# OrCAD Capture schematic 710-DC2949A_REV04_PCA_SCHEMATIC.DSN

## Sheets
1 LT8253A: size Custom; company: ANALOG DEVICES; note: DEMO BOARD BILL OF MATERIALS; note: 2MHz 45W AUTOMOTIVE USB TYPE-C PD CHARGER
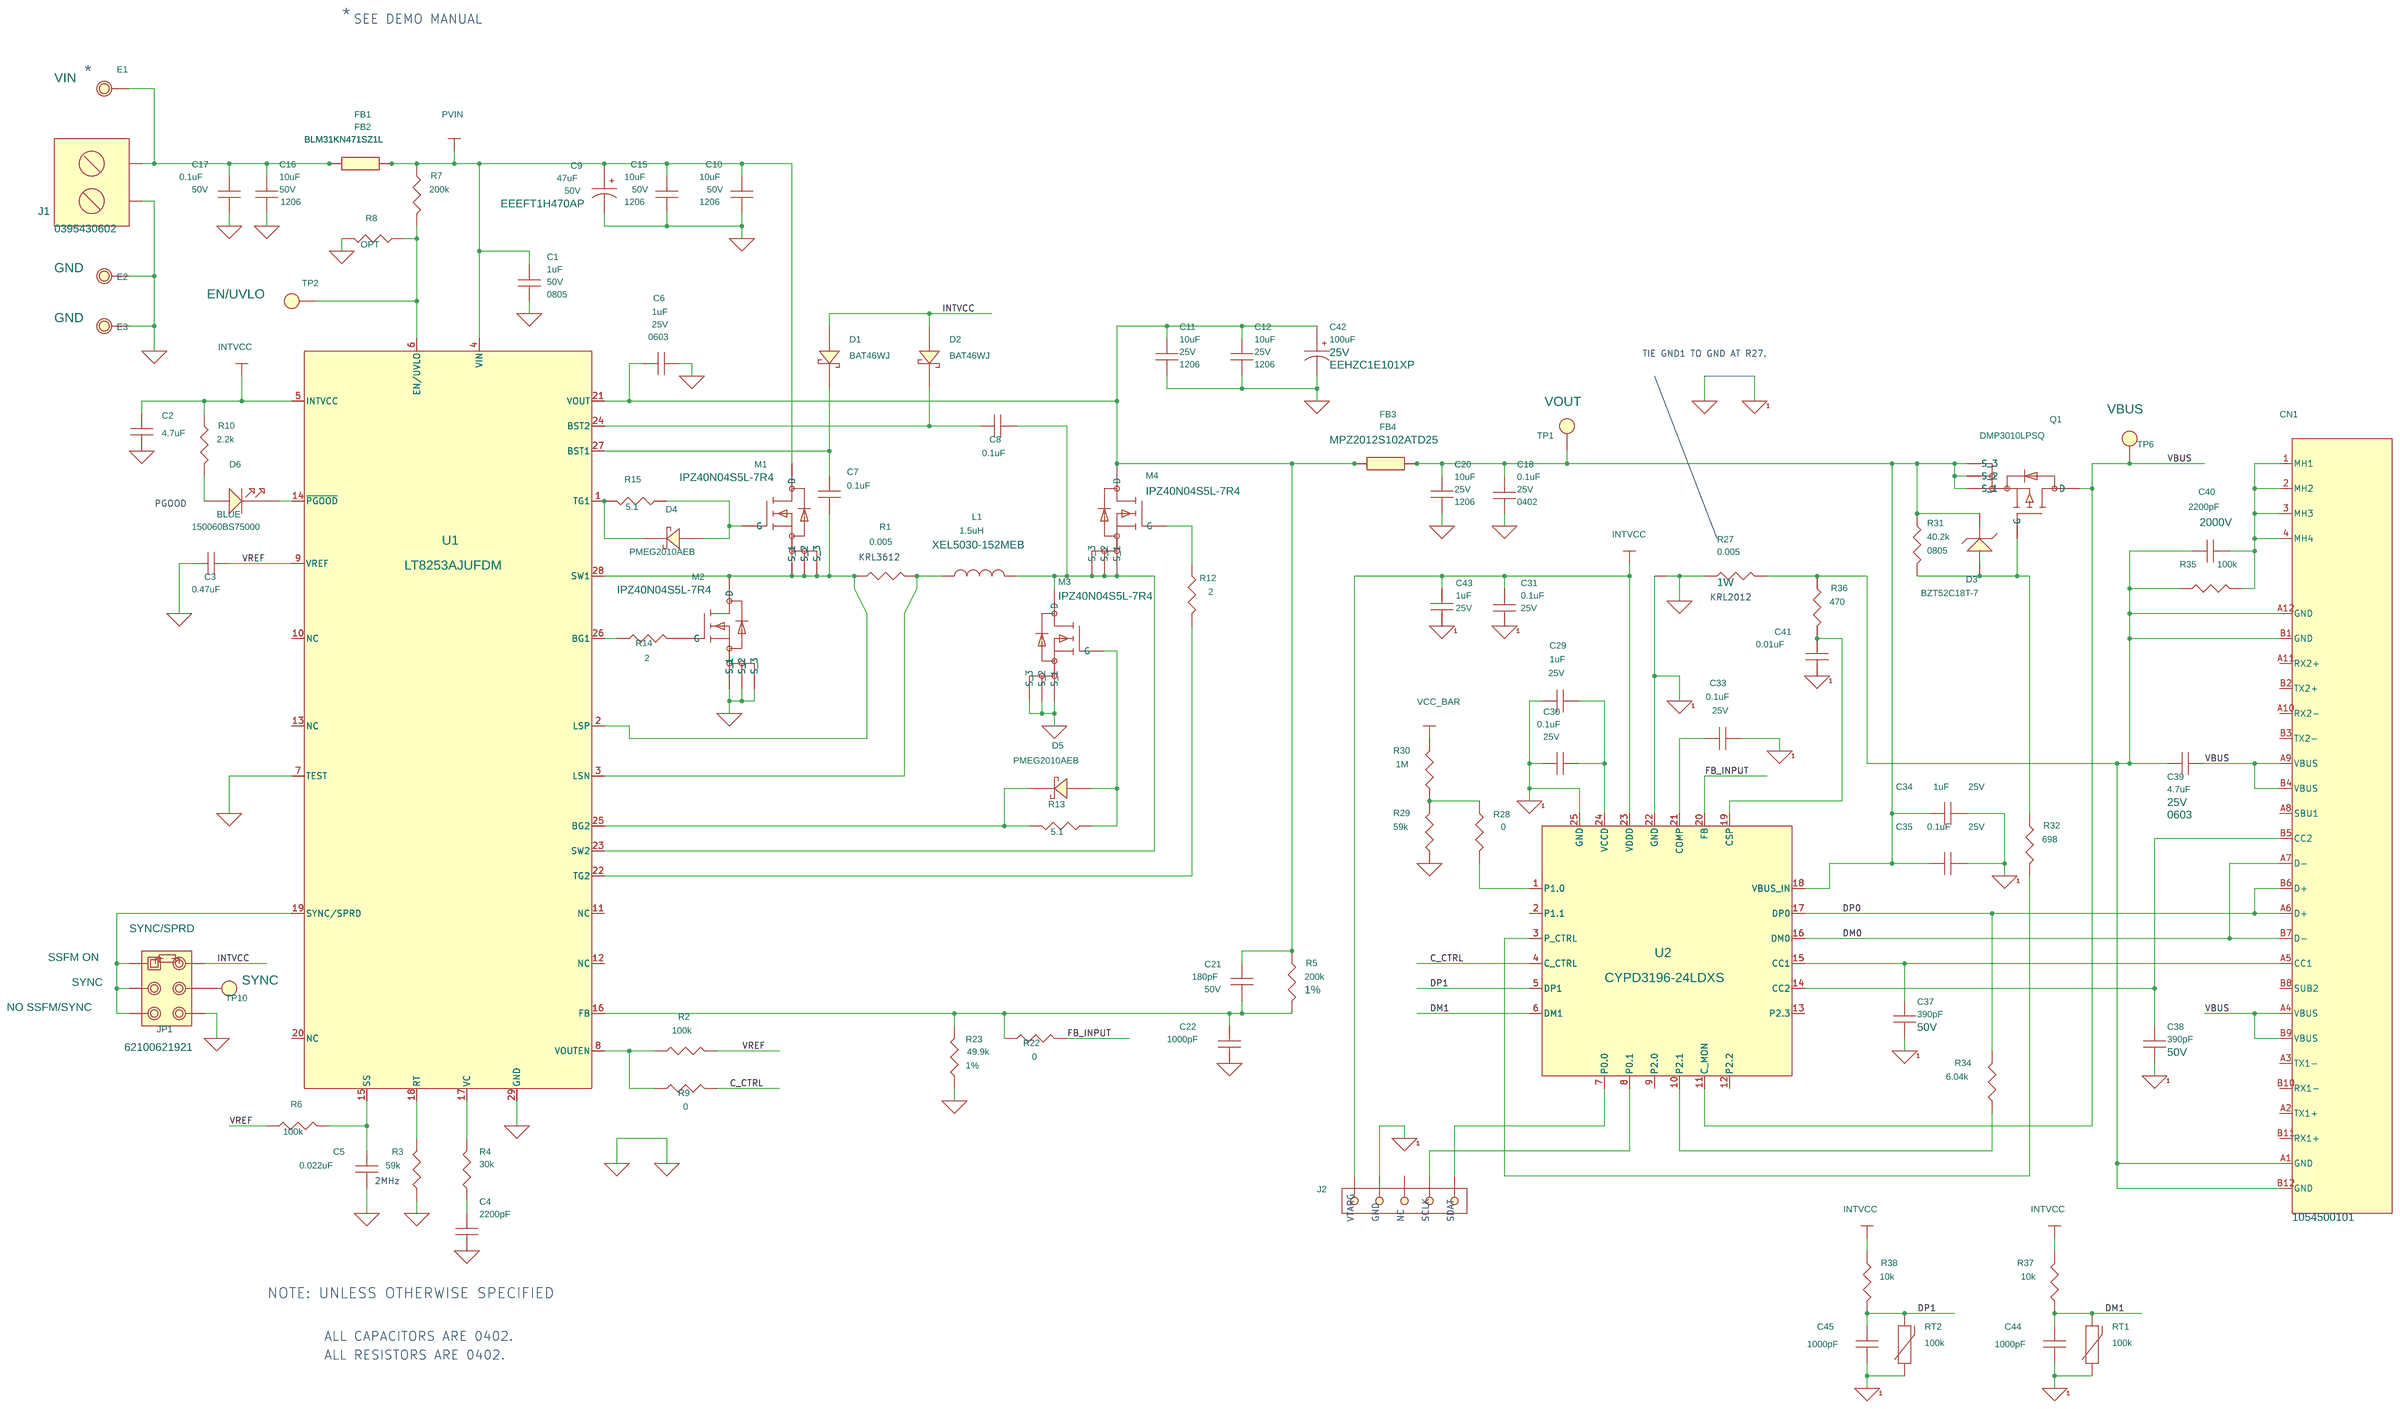
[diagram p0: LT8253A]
2 HARDWARE
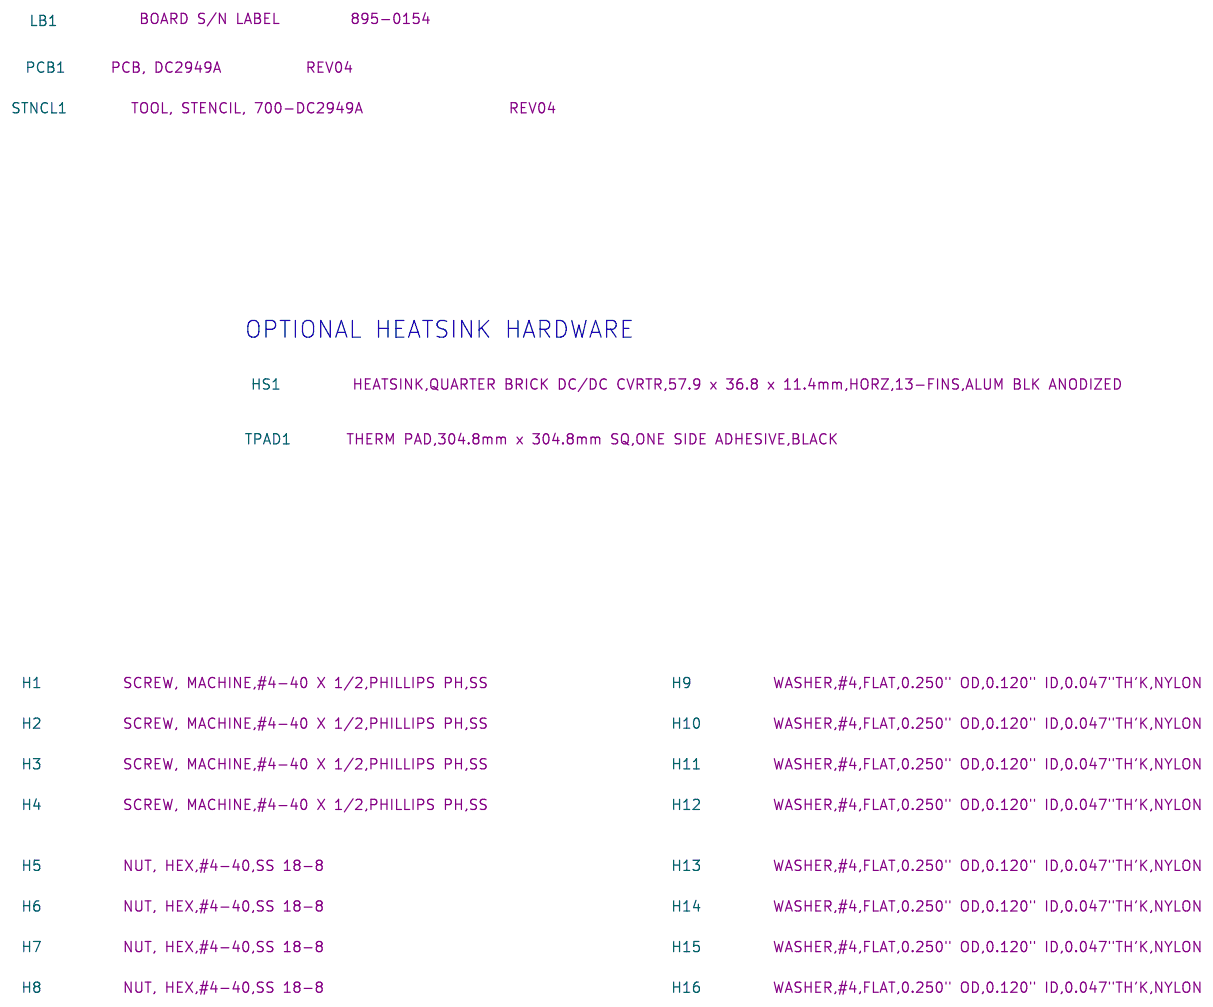
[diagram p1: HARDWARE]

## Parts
sheet HARDWARE
H1  SCREW, MACHINE
H2  SCREW, MACHINE
H3  SCREW, MACHINE
H4  SCREW, MACHINE
H5  NUT, HEX
H6  NUT, HEX
H7  NUT, HEX
H8  NUT, HEX
H9  WASHER,#4,FLAT
H10  WASHER,#4,FLAT
H11  WASHER,#4,FLAT
H12  WASHER,#4,FLAT
H13  WASHER,#4,FLAT
H14  WASHER,#4,FLAT
H15  WASHER,#4,FLAT
H16  WASHER,#4,FLAT
HS1  HEATSINK
LB1  LABEL  [895-0154_REV01]
PCB1  PCB, DC2949A
STNCL1  TOOL, STENCIL, 700-DC2949A
TPAD1  THERM PAD  [UNASSIGNED]
sheet LT8253A
C1  1uF  [CC0805N]
C2  4.7uF  [CC0402N]
C3  0.47uF  [CC0402N]
C4  2200pF  [CC0402N]
C5  0.022uF  [CC0402N]
C6  1uF  [CC0603N]
C7  0.1uF  [CC0402N]
C8  0.1uF  [CC0402N]
C9  47uF  [PANASONIC_FT_6.3X5.8]
C10  10uF  [CC1206N]
C11  10uF  [CC1206N]
C12  10uF  [CC1206N]
C15  10uF  [CC1206N]
C16  10uF  [CC1206N]
C17  0.1uF  [CC0402N]
C18  0.1uF  [CC0402N]
C20  10uF  [CC1206N]
C21  180pF  [CC0402N]
C22  1000pF  [CC0402N]
C29  1uF  [CC0402N]
C30  0.1uF  [CC0402N]
C31  0.1uF  [CC0402N]
C33  0.1uF  [CC0402N]
C34  1uF  [CC0402N]
C35  0.1uF  [CC0402N]
C37  390pF  [CC0402N]
C38  390pF  [CC0402N]
C39  4.7uF  [CC0603N]
C40  2200pF  [CC1808N]
C41  0.01uF  [CC0402N]
C42  100uF  [PANASONIC_ZC_6.3X7.7]
C43  1uF  [CC0402N]
C44  1000pF  [CC0402N]
C45  1000pF  [CC0402N]
CN1  USB3.1  [MOLEX-1054500101]
D1  BAT46WJ  [SOD-323F-N]
D2  BAT46WJ  [SOD-323F-N]
D3  BZT52C18T-7  [SOD-523N]
D4  PMEG2010AEB  [SOD-523N]
D5  PMEG2010AEB  [SOD-523N]
D6  BLUE  [LED_0603]
E1  TEST POINT  [MILLMAX2308]
E2  TEST POINT  [MILLMAX2308]
E3  TEST POINT  [MILLMAX2308]
FB1  470 OHMS@100MHz  [IND1206N]
FB2  470 OHMS@100MHz  [IND1206N]
FB3  1k OHM@100MHz  [IND0805N]
FB4  1k OHM@100MHz  [IND0805N]
J1  TERM. BLOCK  [MOLEX-0395430602]
J2  HDR  [HD1X5-100]
JP1  HDR  [WURTH-62100621921]
L1  1.5uH  [COILCRAFT-XEL5030]
M1  IPZ40N04S5L-7R4  [INFINEON-PG-TSDSON-8-32]
M2  IPZ40N04S5L-7R4  [INFINEON-PG-TSDSON-8-32]
M3  IPZ40N04S5L-7R4  [INFINEON-PG-TSDSON-8-32]
M4  IPZ40N04S5L-7R4  [INFINEON-PG-TSDSON-8-32]
N1  KELVIN NET TIE  [KELVIN-NET-TIE]
Q1  DMP3010LPSQ  [DIODES-POWERDI5060-8]
R1  0.005  [SUSUMU-KRL3216]
R2  100k  [CR0402N]
R3  59k  [CR0402N]
R4  30k  [CR0402N]
R5  200k  [CR0402N]
R6  100k  [CR0402N]
R7  200k  [CR0402N]
R8  OPT  [CR0402N]
R9  0  [CR0402N]
R10  2.2k  [CR0402N]
R12  2  [CR0402N]
R13  5.1  [CR0402N]
R14  2  [CR0402N]
R15  5.1  [CR0402N]
R22  0  [CR0402N]
R23  49.9k  [CR0402N]
R27  0.005  [SUSUMU-KRL2012]
R28  0  [CR0402N]
R29  59k  [CR0402N]
R30  1M  [CR0402N]
R31  40.2k  [CR0805N]
R32  698  [CR0402N]
R34  6.04k  [CR0402N]
R35  100k  [CR0402N]
R36  470  [CR0402N]
R37  10k  [CR0402N]
R38  10k  [CR0402N]
RT1  100k  [CR0603N]
RT2  100k  [CR0603N]
TP1  TEST PAD  [PADSTYLE1]
TP2  TEST PAD  [PADSTYLE1]
TP6  TEST PAD  [PADSTYLE1]
TP10  TEST PAD  [PADSTYLE1]
U1  LT8253AJUFDM  [LTC-UFDM-28-1682]
U2  CYPD3196-24LDXS  [CYPRESS-CYPD3196-24LDXS]
XJP1  SHUNT

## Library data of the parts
H1-H4 = BLANK_PINLESS_MECHANICAL_PART: SCREW, MACHINE,#4-40 X 1/2,PHILLIPS PH,SS; CLASS: MECHANICAL PART; Inventory Qty: 17916; Manufacturer: PENCOM; Manufacturer PN: SC3389; PART_NUMBER: 760-0065
H5-H8 = BLANK_PINLESS_MECHANICAL_PART: NUT, HEX,#4-40,SS 18-8; CLASS: MECHANICAL PART; Inventory Qty: 8116; Manufacturer: PENCOM; Manufacturer PN: NU1043; PART_NUMBER: 761-0005
H9-H16 = BLANK_PINLESS_MECHANICAL_PART: WASHER,#4,FLAT,0.250" OD,0.120" ID,0.047"TH'K,NYLON; CLASS: DISCRETE; Inventory Qty: 4520; Manufacturer: KEYSTONE; Manufacturer PN: 345; PART_NUMBER: 762-0024
HS1 = BLANK_MECHANICAL_PART: HEATSINK,QUARTER BRICK DC/DC CVRTR,57.9 x 36.8 x 11.4mm,HORZ,13-FINS,ALUM BLK ANODIZED; CLASS: DISCRETE; Inventory Qty: 440; Manufacturer: Wakefield-Vette; Manufacturer PN: 537-45AB; PART_NUMBER: 930-0009
LB1 = BLANK_LABEL: LABEL SPEC, DEMO BOARD SERIAL NUMBER; Inventory Qty: 0; Manufacturer: BRADY; Manufacturer PN: THT-96-717-10; PART_FIELD_01: BOARD S/N LABEL; PART_NUMBER: 895-0154
PCB1 = BLANK_PCB_PART: BOM Notes: REV04; CLASS: DISCRETE; Inventory Qty: 180; Manufacturer: ADI APPROVED SUPPLIER; Manufacturer PN: 600-DC2949A; PART_NUMBER: 600-DC2949A
STNCL1 = BLANK_STENCIL_PART: BOM Notes: REV04; CLASS: DISCRETE; Inventory Qty: 0; Manufacturer: ADI APPROVED SUPPLIER; Manufacturer PN: 830-DC2949A; PART_NUMBER: 830-DC2949A
TPAD1 = BLANK_MECHANICAL_PART: THERM PAD,304.8mm x 304.8mm SQ,ONE SIDE ADHESIVE,BLACK; CLASS: DISCRETE; Inventory Qty: 5; Manufacturer: HENKEL; Manufacturer PN: SP1200-0.009-00-1212; PART_NUMBER: 930-1000; Package Size: 304.80mm x 304.80mm
C1 = CAP: CAP.,1uF,X7R,50V,10%,0805,AEC-Q200; CLASS: DISCRETE; Dielectric Type: X7R; FPLIST: CC0805N,CC0805L,CC0805M; Inventory Qty: 8866; Manufacturer: MURATA; Manufacturer PN: GCM21BR71H105KA03L; PART_NUMBER: 150-1750; Package Size: 0805; Rated Voltage: 50V; Temperature Coefficient: X7R; Tolerance: 10%
C2 = CAP: CAP.,4.7uF,X5R,6.3V,20%,0402,AEC-Q200; CLASS: DISCRETE; Dielectric Type: X5R; FPLIST: CC0402N,CC0402M,CC0402L; Inventory Qty: 10830; Manufacturer: Taiyo Yuden; Manufacturer PN: JMK105BBJ475MVHF; PART_NUMBER: 150-1751; Package Size: 0402; Rated Voltage: 6.3V; Temperature Coefficient: X5R; Tolerance: 20%
C3 = CAP: CAP.,0.47uF,X5R,25V,10%,0402,AEC-Q200, NO SUBS. ALLOWED; CLASS: DISCRETE; Dielectric Type: X5R; FPLIST: CC0402N,CC0402L,CC0402M; Inventory Qty: 11830; Manufacturer: MURATA; Manufacturer PN: GRT155R61E474KE01D; PART_NUMBER: 150-2591; Package Size: 0402; Rated Voltage: 25V; Temperature Coefficient: X5R; Tolerance: 10%
C4 = CAP: CAP.,2200pF,X7R,50V,10%,0402,AEC-Q200; CLASS: DISCRETE; Dielectric Type: X7R; FPLIST: CC0402N,CC0402L,CC0402M,CC0402N_022,CC0402L_022,CC0402M_022; Inventory Qty: 49890; Manufacturer: KEMET; Manufacturer PN: C0402C222K5RACAUTO; PART_NUMBER: 150-1773; Package Size: 0402; Rated Voltage: 50V; Temperature Coefficient: X7R; Tolerance: 10%
C5 = CAP: CAP.,0.022uF,X7R,25V,10%,0402,AEC-Q200; CLASS: DISCRETE; Dielectric Type: X7R; FPLIST: CC0402N,CC0402M,CC0402L; Inventory Qty: 23940; Manufacturer: MURATA; Manufacturer PN: GCM155R71E223KA55D; PART_NUMBER: 150-1753; Package Size: 0402; Rated Voltage: 25V; Temperature Coefficient: X7R; Tolerance: 10%
C6 = CAP: CAP.,1uF,X7R,25V,10%,0603,AEC-Q200; CLASS: DISCRETE; Dielectric Type: X7R; FPLIST: CC0603N,CC0603L,CC0603M; Inventory Qty: 54674; Manufacturer: MURATA; Manufacturer PN: GCM188R71E105KA64D; PART_NUMBER: 150-0291; Package Size: 0603; Rated Voltage: 25V; Tolerance: 10%
C7 C8 = CAP: CAP.,0.1uF,X7R,16V,10%,0402,AEC-Q200; CLASS: DISCRETE; Dielectric Type: X7R; FPLIST: CC0402N,CC0402L,CC0402M; Inventory Qty: 23525; Manufacturer: MURATA; Manufacturer PN: GCM155R71C104KA55D; PART_NUMBER: 150-0506; Package Size: 0402; Rated Voltage: 16V; Tolerance: 10%
C9 = CAP_P_ALT: CAP.,47uF,ALUM ELECT,50V,20%,6.3x5.8mm SMD,RADIAL,AEC-Q200; CLASS: DISCRETE; Dielectric Type: ALUM ELECT; Inventory Qty: 2350; Manufacturer: PANASONIC; Manufacturer PN: EEEFT1H470AP; PART_NUMBER: 150-1754; Package Size: 6.3x5.8mm SMD,RADIAL; Package Type: Surface Mount; Rated Voltage: 50V; Tolerance: 20%
C10 C15 C16 = CAP: CAP.,10uF,X5R,50V,10%,1206,AEC-Q200; CLASS: DISCRETE; Dielectric Type: X5R; FPLIST: CC1206N,CC1206L,CC1206M; Inventory Qty: 9550; Manufacturer: MURATA; Manufacturer PN: GRT31CR61H106KE01L; PART_NUMBER: 150-1755; Package Size: 1206; Package Type: SMD; Rated Voltage: 50V; Tolerance: 10%
C11 C12 C20 = CAP: CAP.,10uF,X7R,25V,10%,1206,AEC-Q200; CLASS: DISCRETE; Dielectric Type: X7R; FPLIST: CC1206N,CC1206L,CC1206M; Inventory Qty: 14272; Manufacturer: TAIYO YUDEN; Manufacturer PN: TMK316AB7106KLHT; PART_NUMBER: 150-2466; Package Size: 1206; Package Type: SMD; Rated Voltage: 25V; Tolerance: 10%
C17 = CAP: CAP.,0.1uF,X7R,50V,10%,0402,AEC-Q200; CLASS: DISCRETE; Dielectric Type: X7R; FPLIST: CC0402N,CC0402L,CC0402M; Inventory Qty: 75030; Manufacturer: MURATA; Manufacturer PN: GCM155R71H104KE02D; PART_NUMBER: 150-2620; Package Size: 0402; Rated Voltage: 50V; Temperature Coefficient: X7R; Tolerance: 10%
C18 C30 C31 C33 C35 = CAP: CAP.,0.1uF,X7R,25V,10%,0402,AEC-Q200; CLASS: DISCRETE; Dielectric Type: X7R; FPLIST: CC0402N,CC0402L,CC0402M; Inventory Qty: 23030; Manufacturer: MURATA; Manufacturer PN: GCM155R71E104KE02D; PART_NUMBER: 150-1756; Package Size: 0402; Rated Voltage: 25V; Temperature Coefficient: X7R; Tolerance: 10%
C21 = CAP: CAP.,180pF,C0G/NP0,50V,5%,0402; CLASS: DISCRETE; Dielectric Type: C0G/NP0; FPLIST: CC0402N,CC0402L,CC0402M; Inventory Qty: 89552; Manufacturer: MURATA; Manufacturer PN: GRM1555C1H181JA01D; PART_NUMBER: 150-1703; Package Size: 0402; Rated Voltage: 50V; Temperature Coefficient: C0G; Tolerance: 5%
C22 C44 C45 = CAP: CAP.,1000pF,X7R,50V,10%,0402,AEC-Q200; CLASS: DISCRETE; Dielectric Type: X7R; Inventory Qty: 13560; Manufacturer: MURATA; Manufacturer PN: GCM155R71H102KA37D; PART_NUMBER: 150-1752; Package Size: 0402; Package Type: SMD; Rated Voltage: 50V; Tolerance: 10%
C29 C34 C43 = CAP: CAP.,1uF,X5R,25V,10%,0402,AEC-Q200; CLASS: DISCRETE; Dielectric Type: X5R; FPLIST: CC0402N,CC0402L,CC0402M; Inventory Qty: 31250; Manufacturer: MURATA; Manufacturer PN: GRT155R61E105KE01D; PART_NUMBER: 150-0749; Package Size: 0402; Rated Voltage: 25V; Tolerance: 10%
C37 C38 = CAP: CAP.,390pF,X7R,50V,10%,0402,AEC-Q200; CLASS: DISCRETE; Dielectric Type: X7R; Inventory Qty: 13660; Manufacturer: KEMET; Manufacturer PN: C0402C391K5RACAUTO; PART_NUMBER: 150-1757; Package Size: 0402; Package Type: SMD/SMT; Rated Voltage: 50V; Tolerance: 10%
C39 = CAP: CAP.,4.7uF,X5R,25V,10%,0603,AEC-Q200, NO SUBS. ALLOWED; CLASS: DISCRETE; Dielectric Type: X5R; FPLIST: CC0603N,CC0603L,CC0603M; Inventory Qty: 13830; Manufacturer: MURATA; Manufacturer PN: GRT188R61E475KE13D; PART_NUMBER: 150-2589; Package Size: 0603; Rated Voltage: 25V; Tolerance: 10%
C40 = CAP: CAP.,2200pF,X7R,2000V,10%,1808; CLASS: DISCRETE; Dielectric Type: X7R; Inventory Qty: 6680; Manufacturer: AVX; Manufacturer PN: 1808GC222KAT1A; PART_NUMBER: 150-1760; Package Size: 1808; Rated Voltage: 2000V; Temperature Coefficient: X7R; Tolerance: 10%
C41 = CAP: CAP.,0.01uF,X7R,25V,10%,0402,AEC-Q200; CLASS: DISCRETE; Dielectric Type: X7R; FPLIST: CC0402N,CC0402L,CC0402M; Inventory Qty: 27993; Manufacturer: MURATA; Manufacturer PN: GCM155R71E103KA37D; PART_NUMBER: 150-0517; Package Size: 0402; Rated Voltage: 25V; Tolerance: 10%
C42 = CAP_P_ALT: CAP.,100uF,HBRID,25V,20%,6.3x7.7mm,D8,SMD,RADIAL,AEC-Q200; CLASS: DISCRETE; Dielectric Type: HBRID; Inventory Qty: 1340; Manufacturer: PANASONIC; Manufacturer PN: EEHZC1E101XP; PART_NUMBER: 150-1758; Package Size: 6.3x7.7mm,D8,SMD,RADIAL; Package Type: Surface Mount; Rated Voltage: 25V; Tolerance: 20%
CN1 = MOLEX-1054500101_ALT1: CONN.,USB3.1,RCPT,24POS,1PORT,0.5mm,R/A,HORZ,SMT,TYPE C; CLASS: IO; Inventory Qty: 4028; Manufacturer: MOLEX; Manufacturer PN: 1054500101; PART_NUMBER: 250-0769
D1 D2 = DIODE_SCHOTTKY_A_ALT: DIODE,SCHOTTKY,100V,250mA,SOD-323F,AEC-Q101; CLASS: DISCRETE; FPLIST: SOD-323F-N,SOD-323F-L,SOD-323F-M; Inventory Qty: 6994; Manufacturer: NEXPERIA; Manufacturer PN: BAT46WJ,115; Max Forward Current or Rated Power: 250mA; PART_NUMBER: 210-0235; Package Type: SOD-323F; Rated Voltage or Zener Voltage: 100V
D3 = ZENER_ALT: DIODE,ZENER,18V,300mW,SOD-523,AEC-Q101; CLASS: DISCRETE; FPLIST: SOD-523N,SOD-523L,SOD-523M; Inventory Qty: 960; Manufacturer: DIODES INC.; Max Forward Current or Rated Power: 300mW; PART_NUMBER: 210-0493; Package Size: SC-79, SOD-523; Package Type: SOD-523; Rated Voltage or Zener Voltage: 18V
D4 D5 = DIODE_SCHOTTKY_A_ALT: DIODE,SCHOTTKY,20V,1A,SOD-523,AEC-Q101; CLASS: DISCRETE; Inventory Qty: 4584; Manufacturer: NEXPERIA; Manufacturer PN: PMEG2010AEB,115; PART_NUMBER: 210-0272; Package Size: SOD-523; Package Type: SOD-523; Rated Voltage or Zener Voltage: 20V
D6 = LED_ALT: LED,BLUE,WATERCLEAR,0603; CLASS: DISCRETE; Inventory Qty: 4418; Manufacturer: WURTH ELEKTRONIK; Manufacturer PN: 150060BS75000; PART_NUMBER: 270-0092; Package Size: 0603; Package Type: 0603
E1 = TEST_POINT_.156_MILL-MAX_2308_A: TEST POINT,TURRET,0.064" MTG. HOLE,PCB 0.062" THK; CLASS: IO; Inventory Qty: 918180; Manufacturer: MILL-MAX; Manufacturer PN: 2308-2-00-80-00-00-07-0; PART_FIELD_1: VIN; PART_FIELD_2: 9V-18V; PART_NUMBER: 260-0004
E2 E3 = TEST_POINT_.156_MILL-MAX_2308_A: TEST POINT,TURRET,0.064" MTG. HOLE,PCB 0.062" THK; CLASS: IO; Inventory Qty: 918180; Manufacturer: MILL-MAX; Manufacturer PN: 2308-2-00-80-00-00-07-0; PART_FIELD_1: GND; PART_NUMBER: 260-0004
FB1 FB2 = FERRITEBEAD_ALT1: IND.,470 OHMS@100MHz,FERRITE BEAD,25%,4A,20mOHMS,1206,AEC-Q200; CLASS: DISCRETE; FPLIST: IND1206N,IND1206L,IND1206M; Inventory Qty: 10352; Manufacturer: MURATA; Manufacturer PN: BLM31KN471SZ1L; PART_NUMBER: 200-0775; Package Size: 1206; Tolerance: 25%
FB3 FB4 = FERRITEBEAD_ALT1: IND.,1k OHM@100MHz,FERRITE BEAD,25%,1.5A,150mOHMS,0805,AEC-Q200; CLASS: DISCRETE; FPLIST: IND0805N,IND0805L,IND0805M; Inventory Qty: 24204; Manufacturer: TDK; Manufacturer PN: MPZ2012S102ATD25; PART_NUMBER: 200-0508; Package Size: 0805; Tolerance: 25%
J1 = TERMINAL_BLOCK_WITH_SCREW: CONN.,TERM. BLOCK,1x2,5mm,SIDE ENTRY,VERT,THT; CLASS: IO; Inventory Qty: 1350; Manufacturer: MOLEX; Manufacturer PN: 0395430602; PART_NUMBER: 250-0936
J2 = HDR1X5: CONN.,HDR,MALE,1x5,2.54mm,VERT,ST,THT; CLASS: IO; FPLIST: HD1X5-100,HDR-TSW-105-07-L-S; Inventory Qty: 10560; Manufacturer: SAMTEC; Manufacturer PN: TSW-105-07-L-S; PART_NUMBER: 250-0599
JP1 = HDR2X3_ALT1: CONN.,HDR,MALE,2x3,2mm,VERT,ST,SMD; 10th Part Field: NO SSFM/SYNC; 11th Part Field: SYNC; 13tht Part Field: SYNC/SPRD; 9th Part Field: SSFM ON; CLASS: IO; Inventory Qty: 2642; Manufacturer: WURTH ELEKTRONIK; Manufacturer PN: 62100621921; PART_NUMBER: 250-0937
L1 = IND: IND.,1.5uH,PWR,SHIELDED,20%,12.2A,11.9mOHMS,5.48mmX5.28mm,AEC-Q200; CLASS: DISCRETE; Inventory Qty: 940; Manufacturer: COILCRAFT; Manufacturer PN: XEL5030-152MEB; PART_NUMBER: 200-0724; Package Size: 5.48mmX5.28mm; Tolerance: 20%
M1-M4 = 5P_N-CH_TYPE1C: XSTR.,MOSFET,N-CH,40V,40A,PG-TSDSON-8-32,AEC-Q101; CLASS: DISCRETE; Inventory Qty: 4760; Manufacturer: INFINEON; PART_NUMBER: 240-0288; Package Size: 8-PowerTDFN; Package Type: PG-TSDSON-8-32; Rated Voltage: 40V
N1 = NET_TIE_A_0: PCB KELVIN NET TIE; CLASS: IO
Q1 = 5P_P-CH_TYPE1C: XSTR.,MOSFET,P-CH,30V,36A,PowerDI5060-8,AEC-Q101; CLASS: DISCRETE; Inventory Qty: 3330; Manufacturer: DIODES INC.; Manufacturer PN: DMP3010LPSQ-13; PART_NUMBER: 240-0466; Package Size: 8-PowerTDFN; Package Type: PowerDI5060-8; Rated Power: 2.18W (Ta); Rated Voltage: 30V
R1 = RES: RES.,0.005 OHM,1%,1.5W,1206,LONG-SIDE TERM,KRL3216,METAL,SENSE,AEC-Q200; CLASS: DISCRETE; Inventory Qty: 2330; Manufacturer: SUSUMU; Manufacturer PN: KRL3216E-C-R005-F-T1; PART_NUMBER: 100-0664; Package Size: 1206,LONG-SIDE TERM; Rated Power: 1.5W; Temperature Coefficient: +/-50PPM; Tolerance: 1%
R2 R6 R35 = RES: RES.,100k OHMS,5%,1/16W,0402,AEC-Q200; CLASS: DISCRETE; FPLIST: CR0402N,CR0402L,CR0402M; Inventory Qty: 61412; Manufacturer: NIC; Manufacturer PN: NRC04J104TRF; PART_NUMBER: 100-0359; Package Size: 0402; Rated Power: 1/16W; Temperature Coefficient: 200ppm/C; Tolerance: 5%
R3 R29 = RES: RES.,59k OHMS,1%,1/16W,0402,AEC-Q200; CLASS: DISCRETE; FPLIST: CR0402N,CR0402L,CR0402M; Inventory Qty: 53926; Manufacturer: NIC; Manufacturer PN: NRC04F5902TRF; PART_NUMBER: 100-0515; Package Size: 0402; Rated Power: 1/16W; Temperature Coefficient: 100ppm; Tolerance: 1%
R4 = RES: RES.,30k OHMS,1%,1/16W,0402,AEC-Q200; CLASS: DISCRETE; FPLIST: CR0402N,CR0402L,CR0402M; Inventory Qty: 69890; Manufacturer: STACKPOLE ELECTRONICS, INC.; Manufacturer PN: RMCF0402FT30K0; PART_NUMBER: 100-0218; Package Size: 0402; Rated Power: 1/16W; Temperature Coefficient: 100ppm/C; Tolerance: 1%
R5 R7 = RES: RES.,200k OHMS,1%,1/10W,0402,AEC-Q200; CLASS: DISCRETE; Inventory Qty: 19138; Manufacturer: KOA SPEER; Manufacturer PN: RK73H1ETTP2003F; PART_NUMBER: 100-0823; Package Size: 0402; Rated Power: 1/10W; Temperature Coefficient: 100ppm; Tolerance: 1%
R8 = RES: RES., OPTION, 0402; CLASS: DISCRETE; FPLIST: CR0402N,CR0402L,CR0402M; PART_NUMBER: 100-0357; Package Size: 0402
R9 R22 R28 = RES: RES.,0 OHM,1/10W,0402,AEC-Q200; CLASS: DISCRETE; FPLIST: CR0402N,CR0402L,CR0402M; Inventory Qty: 33594; Manufacturer: PANASONIC; Manufacturer PN: ERJ2GE0R00X; PART_NUMBER: 100-2408; Package Size: 0402; Rated Power: 1/10W
R10 = RES: RES.,2.2k OHMS,1%,1/10W,0402,AEC-Q200; CLASS: DISCRETE; FPLIST: CR0402N,CR0402L,CR0402M; Inventory Qty: 39960; Manufacturer: PANASONIC; Manufacturer PN: ERJ2RKF2201X; PART_NUMBER: 100-1681; Package Size: 0402; Rated Power: 1/10W; Temperature Coefficient: +/-100PPM; Tolerance: 1%
R12 R14 = RES: RES.,2 OHMS,1%,1/16W,0402,AEC-Q200; CLASS: DISCRETE; Inventory Qty: 49660; Manufacturer: VISHAY; Manufacturer PN: CRCW04022R00FKED; PART_NUMBER: 100-1452; Package Size: 0402; Rated Power: 1/16W; Temperature Coefficient: +/-100ppm; Tolerance: 1%
R13 R15 = RES: RES.,5.1 OHMS,5%,1/10W,0402,AEC-Q200; CLASS: DISCRETE; Inventory Qty: 59660; Manufacturer: PANASONIC; Manufacturer PN: ERJ2GEJ5R1X; PART_NUMBER: 100-1453; Package Size: 0402; Rated Power: 1/10W; Temperature Coefficient: -100/ +600ppm; Tolerance: 5%
R23 = RES: RES.,49.9k OHMS,1%,1/10W,0402,AEC-Q200; CLASS: DISCRETE; FPLIST: CR0402N,CR0402L,CR0402M; Inventory Qty: 77710; Manufacturer: KOA SPEER; Manufacturer PN: RK73H1ETTP4992F; PART_NUMBER: 100-0097; Package Size: 0402; Rated Power: 1/10W; Temperature Coefficient: 100ppm/C; Tolerance: 1%
R27 = RES: RES.,0.005 OHM,1%,1W,0805,LONG-SIDE TERM.,METAL,SENSE,AEC-Q200; CLASS: DISCRETE; Inventory Qty: 2830; Manufacturer: SUSUMU; Manufacturer PN: KRL2012E-M-R005-F-T1; PART_NUMBER: 100-1441; Package Size: 0805,LONG-SIDE TERM.; Rated Power: 1W; Temperature Coefficient: +/-50ppm; Tolerance: 1%
R30 = RES: RES.,1M OHM,5%,1/16W,0402,AEC-Q200; CLASS: DISCRETE; FPLIST: CR0402N,CR0402L,CR0402M; Inventory Qty: 25940; Manufacturer: VISHAY; Manufacturer PN: CRCW04021M00JNED; PART_NUMBER: 100-0321; Package Size: 0402; Rated Power: 1/16W; Temperature Coefficient: 200ppm; Tolerance: 5%
R31 = RES: RES.,40.2k OHMS,1%,1/8W,0805,AEC-Q200; CLASS: DISCRETE; FPLIST: CR0805N,CR0805L,CR0805M; Inventory Qty: 29960; Manufacturer: PANASONIC; Manufacturer PN: ERJ6ENF4022V; PART_NUMBER: 100-2998; Package Size: 0805; Rated Power: 1/8W; Temperature Coefficient: +/-100ppm; Tolerance: 1%
R32 = RES: RES.,698 OHMS,1%,1/16W,0402,AEC-Q200; CLASS: DISCRETE; FPLIST: CR0402N,CR0402L,CR0402M; Inventory Qty: 69960; Manufacturer: STACKPOLE ELECTRONICS, INC.; Manufacturer PN: RMCF0402FT698R; PART_NUMBER: 100-1150; Package Size: 0402; Rated Power: 1/16W; Temperature Coefficient: +/-100PPM; Tolerance: 1%
R34 = RES: RES.,6.04k OHMS,1%,1/16W,0402,AEC-Q200; CLASS: DISCRETE; FPLIST: CR0402N,CR0402L,CR0402M; Inventory Qty: 35946; Manufacturer: NIC; Manufacturer PN: NRC04F6041TRF; PART_NUMBER: 100-0542; Package Size: 0402; Rated Power: 1/16W; Temperature Coefficient: 100ppm; Tolerance: 1%
R36 = RES: RES.,470 OHMS,5%,1/10W,0402,AEC-Q200; CLASS: DISCRETE; FPLIST: CR0402N,CR0402L,CR0402M; Inventory Qty: 59029; Manufacturer: KOA SPEER; Manufacturer PN: RK73B1ETTP471J; PART_NUMBER: 100-0093; Package Size: 0402; Rated Power: 1/10W; Temperature Coefficient: 200ppm/C; Tolerance: 5%
R37 R38 = RES: RES.,10k OHMS,1%,1/10W,0402,AEC-Q200; CLASS: DISCRETE; FPLIST: CR0402N,CR0402L,CR0402M; Inventory Qty: 69353; Manufacturer: KOA SPEER; Manufacturer PN: RK73H1ETTP1002F; PART_NUMBER: 100-0724; Package Size: 0402; Rated Power: 1/10W; Temperature Coefficient: 100ppm; Tolerance: 1%
RT1 RT2 = THERMISTOR-NTC: RES.,100k OHMS,1%,1/10W,0603,4419K,NTC THERMISTOR,AEC-Q200; CLASS: DISCRETE; FPLIST: CR0603N,CR0603L,CR0603M; Inventory Qty: 19660; Manufacturer: TDK; Manufacturer PN: NTCG164KF104FTDS; PART_NUMBER: 122-0013; Package Size: 0603; Rated Power: 1/10W; Tolerance: 1%
TP1 = PAD_STYLE_C: TESTPOINT, PCB COPPER FEATURE; 9th Part Field: VOUT; CLASS: IO; FPLIST: PADSTYLE1,PADSTYLE2,PADSTYLE3,PADSTYLE4,PADSTYLE5,PADSTYLE6,PADSTYLE7,PADSTYLE8; Manufacturer: N/A; Manufacturer PN: N/A
TP2 = PAD_STYLE_C: TESTPOINT, PCB COPPER FEATURE; 9th Part Field: EN/UVLO; CLASS: IO; FPLIST: PADSTYLE1,PADSTYLE2,PADSTYLE3,PADSTYLE4,PADSTYLE5,PADSTYLE6,PADSTYLE7,PADSTYLE8; Manufacturer: N/A; Manufacturer PN: N/A
TP6 = PAD_STYLE_C: TESTPOINT, PCB COPPER FEATURE; 9th Part Field: VBUS; CLASS: IO; FPLIST: PADSTYLE1,PADSTYLE2,PADSTYLE3,PADSTYLE4,PADSTYLE5,PADSTYLE6,PADSTYLE7,PADSTYLE8; Manufacturer: N/A; Manufacturer PN: N/A
TP10 = PAD_STYLE_C: TESTPOINT, PCB COPPER FEATURE; 9th Part Field: SYNC; CLASS: IO; FPLIST: PADSTYLE1,PADSTYLE2,PADSTYLE3,PADSTYLE4,PADSTYLE5,PADSTYLE6,PADSTYLE7,PADSTYLE8; Manufacturer: N/A; Manufacturer PN: N/A
U1 = LT8253A-UFD: IC,SYN. 4-SWITCH BUCK-BOOST CTRLR,QFN-28,AEC-Q200; CLASS: IC; Inventory Qty: 0; Manufacturer: ANALOG DEVICES; Manufacturer PN: LT8253AJUFDM#WPBF; PART_NUMBER: LT8253AJUFDM#WPBF; Package Size: QFN-28; Package Type: QFN-28
U2 = CYPRESS-CYPD3196-24LDXS: IC,USB TYPE-C PORT CONTROLER,QFN-24,AEC-Q100; CLASS: IC; Inventory Qty: 0; Manufacturer: CYPRESS; PART_NUMBER: 280-0704; Package Type: QFN-24
XJP1 = SHUNT_2MM_C: CONN.,SHUNT,FEMALE,2 POS,2mm; CLASS: IO; Inventory Qty: 68564; Manufacturer: Wurth Elektronik; Manufacturer PN: 60800213421; PART_NUMBER: 250-0485

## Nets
GND: C1.1 C2.2 C3.2 C4.2 C5.2 C6.1 C9.2 C10.2 C11.2 C12.2 C15.2 C16.2 C17.2 C18.1 C20.2 C22.2 C42.2 E2.1 E3.1 J1.1 JP1.6 M2.1(S) M2.2(S) M2.3(S) M3.1(S) M3.2(S) M3.3(S) N1.2 R3.2 R8.2 R23.2 R27.1 R29.2 U1.7(TEST) U1.29(GND)
GND1: C29.1 C30.1 C31.1 C33.2 C34.2 C35.2 C37.2 C38.2 C41.2 C43.2 C44.2 C45.2 J2.2 N1.1 RT1.2 RT2.2 U2.22(GND) U2.25(GND)
PVIN: C1.2 C9.1 C10.1 C15.1 FB1.2 FB2.2 M1.5(D) R7.1 R30.1 U1.4(VIN)
VBUS: C39.2 CN1.A4(VBUS) CN1.A9(VBUS) CN1.B4(VBUS) CN1.B9(VBUS) Q1.5(D) TP6.1 U2.11(C_MON)
C_CTRL: R9.1 U2.4(C_CTRL)
DM0: CN1.A7(D-) CN1.B7(D-) U2.16(DM0)
DM1: C44.1 R37.2 RT1.1 U2.6(DM1)
DP0: CN1.A6(D+) CN1.B6(D+) R34.1 U2.17(DP0)
DP1: C45.1 R38.2 RT2.1 U2.5(DP1)
FB_INPUT: R22.1 U2.20(FB)
INTVCC: C2.1 C31.2 C43.1 D1.2(A) D2.2(A) J2.1 JP1.2 R10.1 R37.1 R38.1 U1.5(INTVCC) U2.23(VDDD)
VREF: C3.1 R2.2 R6.2 U1.9(VREF)
N16994718: C7.1 D1.1(C) U1.27(BST1)
N17028240: C7.2 M1.1(S) M1.2(S) M1.3(S) M2.5(D) R1.1 U1.2(LSP) U1.28(SW1)
N17200393: C16.1 C17.1 E1.1 FB1.1 FB2.1 J1.2
N17465905: C8.2 L1.1 M3.5(D) M4.1(S) M4.2(S) M4.3(S) U1.23(SW2)
N17508110: R14.1 U1.26(BG1)
N17526737: L1.2 R1.2 U1.3(LSN)
N17549063: C6.2 C11.1 C12.1 C21.1 C42.1 FB3.1 FB4.1 M4.5(D) R5.1 U1.21(VOUT)
N17718651: M4.4(G) R12.1
N17732267: C8.1 D2.1(C) U1.24(BST2)
N17868488: R4.1 U1.17(VC)
N17869628: C21.2 C22.1 R5.2 R22.2 R23.1 U1.16(FB)
N17899958: D4.2(A) M1.4(G) R15.2
N17936305: D5.2(A) M3.4(G) R13.1
N17941983: C18.2 C20.1 C34.1 C35.1 D3.1(C) FB3.2 FB4.2 Q1.1(S) Q1.2(S) Q1.3(S) R31.1 TP1.1 U2.18(VBUS_IN)
N17994936: R3.1 U1.18(RT)
N17994940: C5.1 R6.1 U1.15(SS)
N18019105: D4.1(C) R15.1 U1.1(TG1)
N18019363: D5.1(C) R13.2 U1.25(BG2)
N18047388: JP1.1 JP1.3 JP1.5 U1.19(SYNC/SPRD)
N18108001: R2.1 R9.2 U1.8(VOUTEN)
N18132634: R7.2 R8.1 TP2.1 U1.6(EN/UVLO)
N18142515: C29.2 C30.2 U2.24(VCCD)
N18144665: C33.1 U2.21(COMP)
N18148718: C41.1 R36.2 U2.19(CSP)
N18150810: D3.2(A) Q1.4(G) R31.2 R32.1
N18152475: R32.2 U2.3(P_CTRL)
N18156978: J2.5 U2.7(P0.0)
N18157919: J2.4 U2.8(P0.1)
N18159030: R34.2 U2.10(P2.1)
N18161205: C40.2 CN1.1(MH1) CN1.2(MH2) CN1.3(MH3) CN1.4(MH4) R35.2
N18163786: C39.1 C40.1 CN1.A1(GND) CN1.A12(GND) CN1.B1(GND) CN1.B12(GND) R27.2 R35.1 R36.1
N18165019: C37.1 CN1.A5(CC1) U2.15(CC1)
N18165022: C38.1 CN1.B5(CC2) U2.14(CC2)
N18304893: R28.1 R29.1 R30.2
N18305034: R28.2 U2.1(P1.0)
N18382365: R12.2 U1.22(TG2)
N18393486: D6.2(ANODE) R10.2
N18393535: D6.1(CATHODE) U1.14(~{PGOOD})
N18401439: C4.1 R4.2
N18403908: JP1.4 TP10.1
N18403909: M2.4(G) R14.2

Not connected (* = marked no-connect by the designer): CN1 A2(TX1+) A3(TX1-) A8(SBU1) A10(RX2-) A11(RX2+) B2(TX2+) B3(TX2-) B8(SUB2) B10(RX1-) B11(RX1+); J2 3; U1 10(NC) 11(NC) 12(NC) 13(NC) 20(NC); U2 2(P1.1) 9(P2.0) 12(P2.2) 13(P2.3)

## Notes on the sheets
sheet 1
- *
- SEE DEMO MANUAL
- *
- TIE GND1 TO GND AT R27.
- PGOOD
- KRL3612
- KRL2012
- 2MHz
- VTARG
- GND
- NC
- SCLK
- SDAT
- NOTE: UNLESS OTHERWISE SPECIFIED
- ALL CAPACITORS ARE 0402.
- ALL RESISTORS ARE 0402.
sheet 2
- OPTIONAL HEATSINK HARDWARE
